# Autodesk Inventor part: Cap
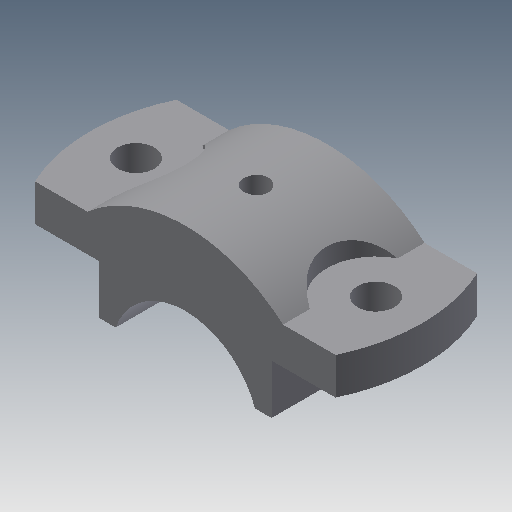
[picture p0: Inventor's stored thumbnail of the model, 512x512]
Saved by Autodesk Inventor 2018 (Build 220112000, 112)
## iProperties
Created: 2009-04
Part Number: Cap
Document SubType Name: Modeling
Designer: Sham
Density: 1 g/cm^3
Material: Generic
Appearance: Default
Mass: 94.0132 g
Surface Area: 184.419 cm^2
Volume: 94.0132 cm^3
Author: Sham
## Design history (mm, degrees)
sketch "Sketch1"
  geometry: L1 (-48.857, 23)-(48.857, 23); L2 (48.857, -23)-(-48.857, -23); A1 r 54 centre (0, 0) between (-48.857, 23) and (-48.857, -23); A2 r 54 centre (0, 0) between (48.857, -23) and (48.857, 23); 1 further point
  constraints: 4 end point, 4 point on circle, 2 centre point, 2 coincident, 1 horizontal, 1 parallel, 1 other
  dimensions: "d3" = 54 radius of A1; "d4" = 54 radius of A2; "d5" = 46 distance between parallel lines of L2 L1; "d6" = 23 distance from line of point (0, 0) L1
extrude "Extrusion1" new body sketch "Sketch1" distance "d7" = 12; taper "d8" = 0 deg
sketch "Sketch3"
  geometry: L1 (20.906, 0)-(20.906, -16); L2 (76.906, -0.137)-(76.906, -16.137); L3 (20.906, -16)-(26.23, -16); L4 (71.532, -16.137)-(76.906, -16.137); L5 (76.906, -0.137)-(76.857, 12); L6 (97.714, 0)-(0, 0) reference; L7 (76.857, 12)-(80.606, 12); L8 (17.108, 12)-(20.906, 12); L9 (20.906, 12)-(20.906, 0); L10 (0, 12)-(97.714, 12) reference; A1 r 24 centre (48.857, -24) between (71.532, -16.137) and (26.23, -16); A2 r 48 centre (48.857, -24) between (80.606, 12) and (17.108, 12); 3 further points
  constraints: 16 end point, 4 point on circle, 3 parallel, 3 perpendicular, 2 centre point, 2 coincident, 2 vertical alignment, 1 collinear, 1 midpoint, 1 vertical, 2 other
  dimensions: "d17" = 48 diameter of A1; "d18" = 16 distance of L1.start L1.end; "d19" = 56 distance between parallel lines of L2 L1; "d21" = 8 vertical distance of A1.centre L1.end; "d22" = 48 radius of A2; "d23" = 0 distance from line of L6 L1.start; "d38" = 31.74902 distance of L7.end point (48.857, 12); "d39" = 28 distance from line of point (48.857, 12) L5
extrude "Extrusion2" join sketch "Sketch3" stored distance "d24" = 12; taper "d25" = 0 deg
sketch "Sketch4"
  geometry: 2 further points
  dimensions: "d26" = 78 distance of point (39, 0) point (-39, 0)
hole "Hole1" sketch "Sketch4" at (-39, 0), (39, 0) diameter "d28" = 12; stored, may be unused: countersink angle "d32" = 90 deg, drill point angle "d34" = 118 deg; dims "d29" = 6, "d30" = 4, "d31" = 2, "d33" = 8
sketch "Sketch5"
  geometry: L1 (-31.749, -23)-(-31.749, 23) reference; L2 (-31.749, 14.263)-(-31.749, -14.263); C1 r 6 at (-39, 0) reference; A1 r 16 centre (-39, 0) between (-31.749, -14.263) and (-31.749, 14.263)
  constraints: 2 end point, 2 point on circle, 1 centre point, 1 coincident, 1 collinear, 1 point on line
  dimensions: "d35" = 16 radius of A1
extrude "Extrusion3" cut sketch "Sketch5" distance "d36" = 12; taper "d37" = 0 deg
mirror "Mirror2"
workplane "Work Plane4"
sketch "Sketch6"
  geometry: L1 (-31.749, 0)-(31.749, 0) reference; 1 further point
  dimensions: "d40" = 23 distance from line of L1 point (0, 23)
hole "Hole2" sketch "Sketch6" at (0, 23) diameter "d41" = 6; stored, may be unused: countersink angle "d45" = 90 deg, drill point angle "d47" = 118 deg; dims "d42" = 6, "d43" = 8, "d44" = 16, "d46" = 8
body "Solid1"
